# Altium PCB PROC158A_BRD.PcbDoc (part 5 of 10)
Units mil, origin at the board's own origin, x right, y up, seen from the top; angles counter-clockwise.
Board outline 3346.45 x 4921.26 mil, 8 copper layers (Top Layer, GND1, SIG1, PWR1, PWR2, SIG2, GND2, Bottom Layer), stack 54.534 mil thick; 718 components, 459 nets, 2307 pads, 1179 vias.
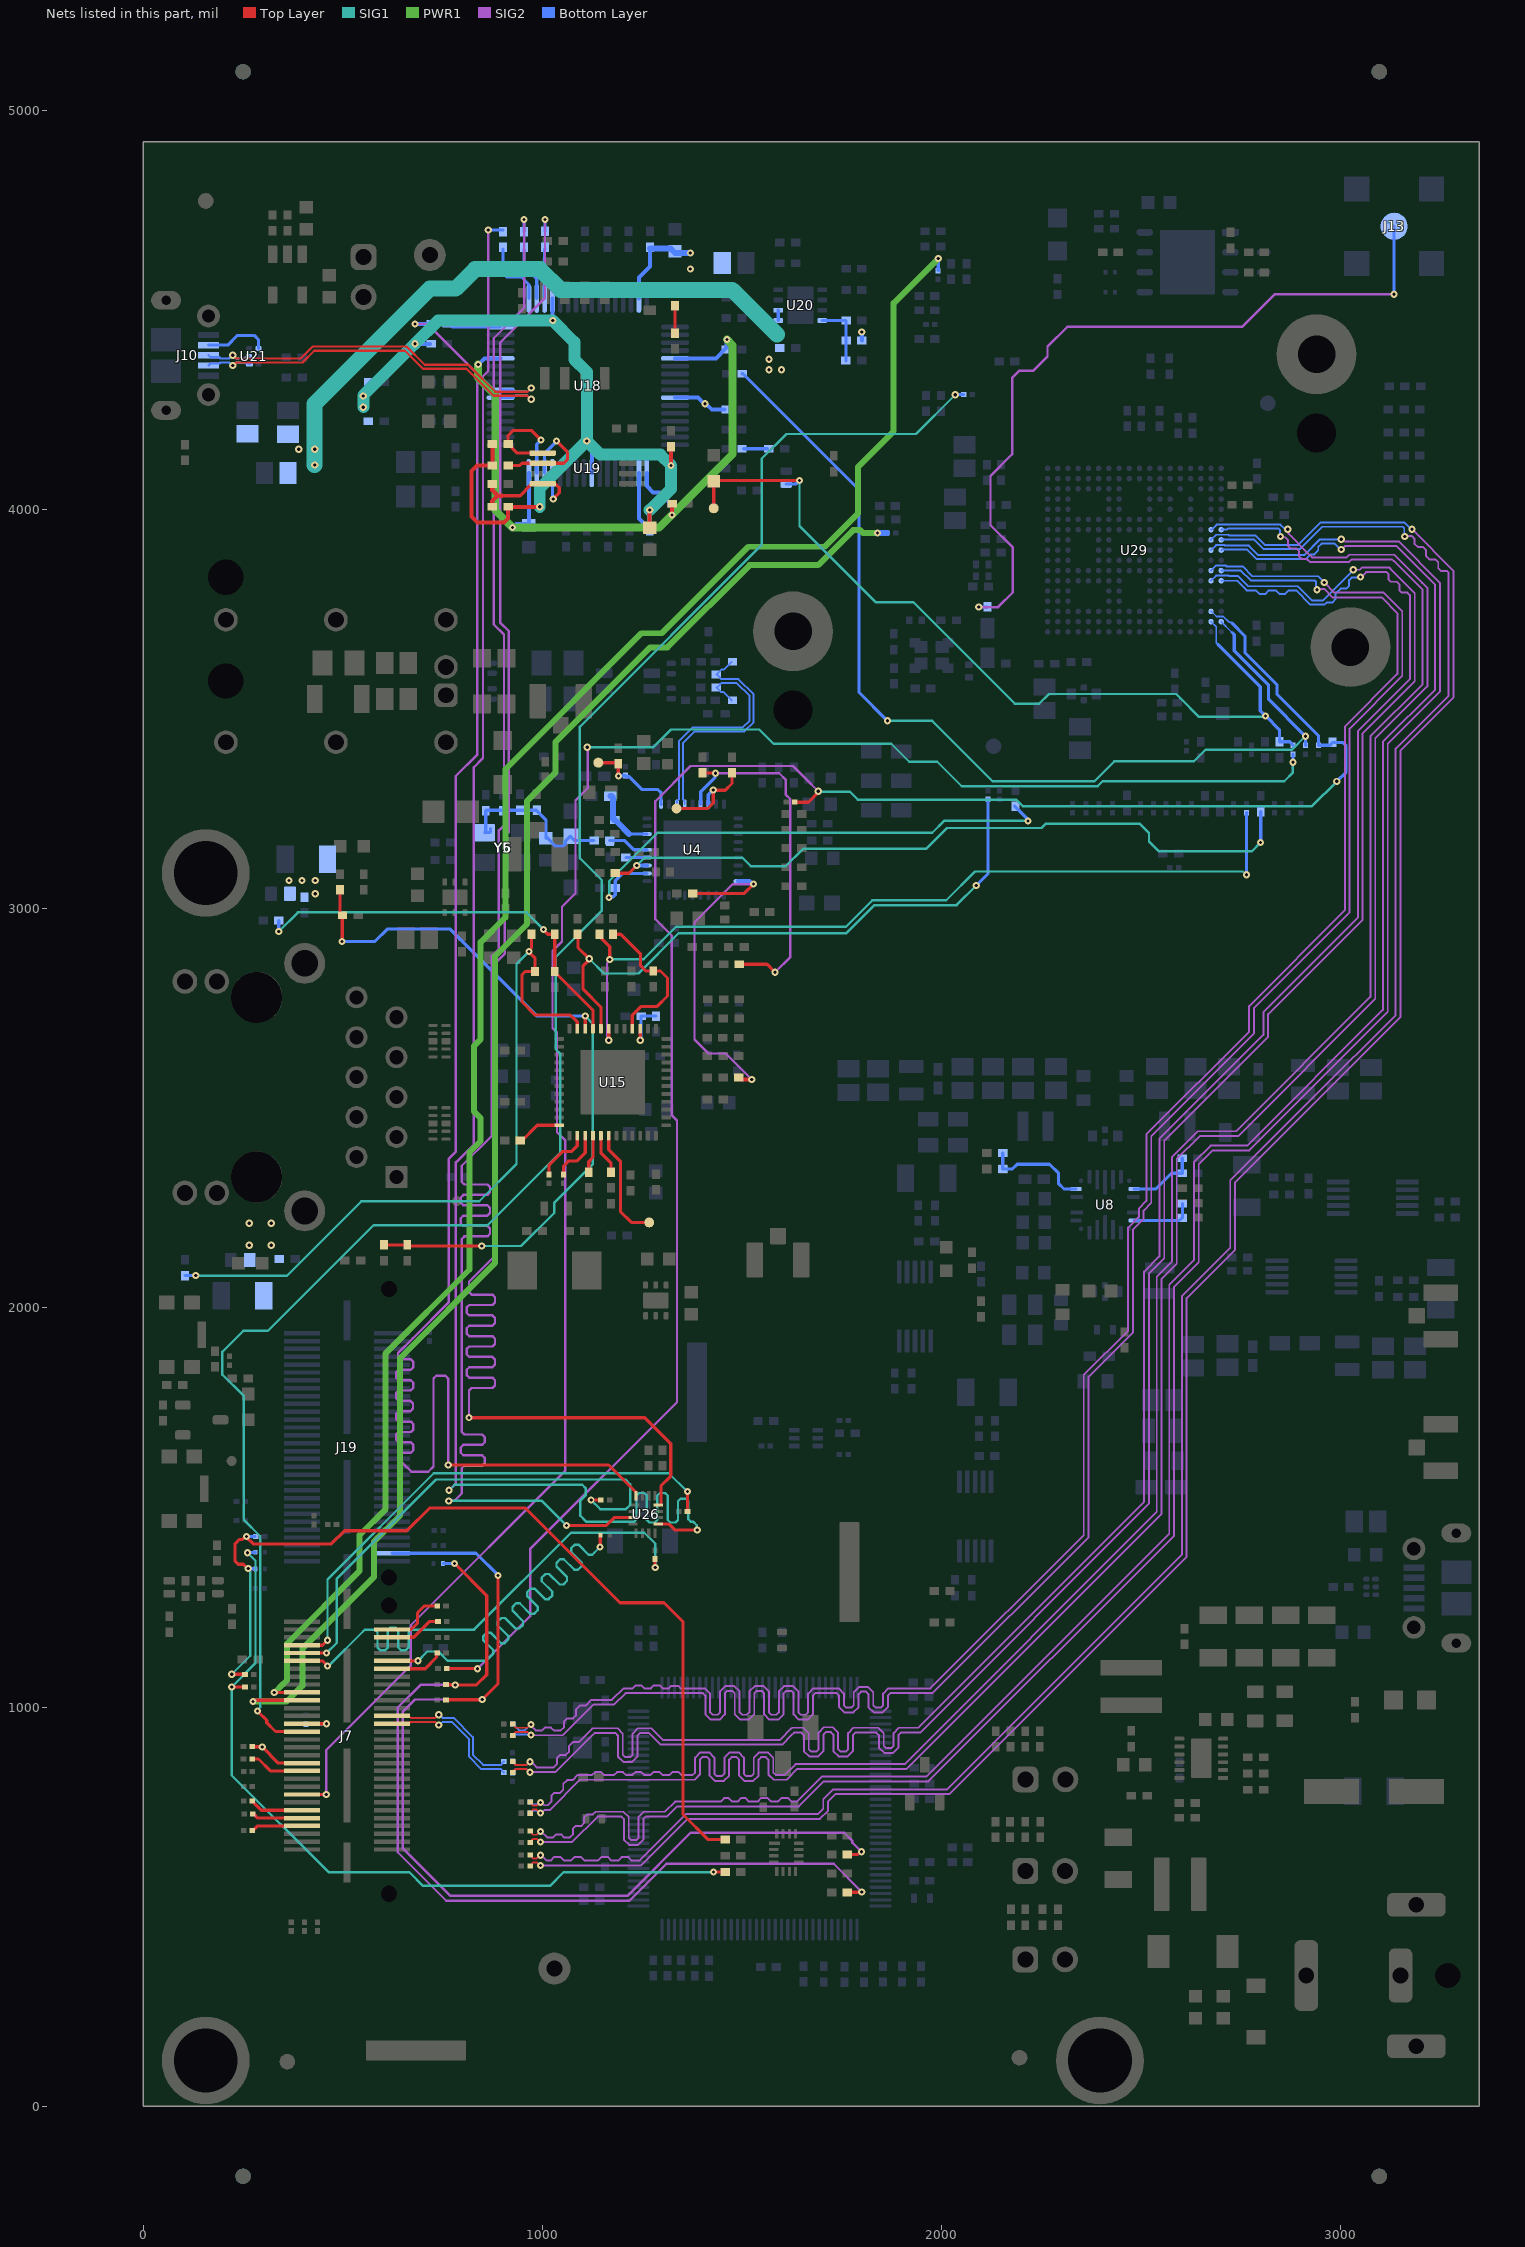
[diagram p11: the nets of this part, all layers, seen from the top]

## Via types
v1: diameter 18, hole 8, Top Layer to Bottom Layer, tented both sides, 1112 vias
v2: diameter 19.68, hole 7.87, Top Layer to Bottom Layer, 28 vias
v3: diameter 20, hole 10, Top Layer to Bottom Layer, tented both sides, 26 vias
v4: diameter 16/18/18/18/18/18/18/16 (per signal layer), hole 8, Top Layer to Bottom Layer, tented both sides, 13 vias

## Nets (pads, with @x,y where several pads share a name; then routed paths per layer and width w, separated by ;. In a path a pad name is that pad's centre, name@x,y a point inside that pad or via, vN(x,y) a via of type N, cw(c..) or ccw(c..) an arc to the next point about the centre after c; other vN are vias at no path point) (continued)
AR_SYNCIN: R17.2 R61.2 R78.2 R115.1 U29.C17 | length 4997.9
  Top Layer w8: R115.1@760.24,1096.36 760.37,1096.24 837.33,1096.24 v1(837.46,1096.11) ; R61.2@1632.43,3266.81 1666.52,3266.81 1691,3291.29 v1(1691,3294)
  SIG1 w6: v1(1691,3294) 1692.12,3292.88 1770.15,3292.88 1789.83,3273.2 2186.63,3273.2 2202.98,3256.85 2927.85,3256.85 v1(2990,3319)
  SIG2 w6: v1(837.46,1096.11) 969,1227.65 969,1395.67 1337,1763.67 1337,2469.46 1324.38,2482.07 1324.38,2932.02 1282.78,2973.62 1282.78,3269.18 1371.04,3357.44 1627.56,3357.44 1660.52,3324.48 v1(1691,3294)
  Bottom Layer w4: U29.C17@2674.75,3744.71 2675.76,3744.71 2688.59,3731.87 2705.63,3731.87 2720.25,3717.25 2725.26,3717.25 2727.51,3715
  Bottom Layer w8: 2727.51,3715 2760,3682.51 2760,3641 2840,3561 2840,3554.13 2840,3537.33 2944,3433.33 R78.2@2944,3409.35 2973.16,3409.35 2979,3415.19 R17.2@2979,3416.66 3004.34,3416.66 3013.13,3407.87 3013.13,3342.13 v1(2990,3319)
AR_WRMRST: D5.2 D9.2 R272.1 R371.1 TP1.1 U29.B17 | length 2231.1
  Top Layer w8: TP1.1@1429,4003 D9.2@1429.01,4070.65 ; D9.2@1429.01,4070.65 1431,4072.64 v1(1643.91,4072.64)
  SIG1 w6: v1(1643.91,4072.64) 1643.91,3958.57 1834.53,3767.95 1929.03,3767.95 2106.08,3590.91 2183.29,3513.7 2244.7,3513.7 2268.75,3537.75 2587.59,3537.75 2598.02,3527.32 2644.88,3480.47 2801.49,3480.47 2801.72,3480.71 2808.71,3480.71 v1(2811,3483)
  Bottom Layer w4: U29.B17@2674.75,3719.11 2687.58,3706.28 2687.58,3666.42 2691.97,3662.03
  Bottom Layer w8: D5.2@1610.48,4063.7 1634.98,4063.7 v1(1643.91,4072.64) ; 2691.97,3662.03 2798.05,3555.95 2798.05,3495.95 v1(2811,3483) 2811.49,3483 2846,3448.49 R272.1@2846,3418.01 2872.13,3418.01 2880,3410.14 R371.1@2880,3409.35
AR_WRMRST_FTDI: R330.2 R362.1 | length 59.5
  Bottom Layer w8: R330.2@1503.76,4152.19 R362.1@1563.24,4152.19
BAW_NC: C121.1 R168.2 R177.2 R185.1 R241.2 R242.2 R248.1 Y5.1 Y6.1 | length 427.8
  Bottom Layer w8: Y5.1@855.78,3190.24 858,3192.47 R185.1@858,3245.81 858.66,3246.47 985.34,3246.47 985.34,3245.82 1008.66,3222.49 R248.1@1008.66,3176.69 ; Y5.1@860.66,3190.84 868.98,3190.84 870.11,3191.97 Y5.1@870.11,3200.28 ; R248.1@1010.63,3178.66 1032.22,3157.07 1052.55,3157.07 1057.23,3161.76 1057.23,3168.55 1070,3181.32 1080.68,3170.64 R242.2@1129.31,3170.64
BSS_UARTA_TX: R131.1 R232.2 U29.B18 | length 2575.2
  SIG1 w6: v1(1864,3470.81) 1976.19,3470.81 2128.2,3318.8 2131.2,3318.8 2382.36,3318.8 2432.86,3369.3 2631.98,3369.3 2661.01,3398.33 2877.33,3398.33 v1@2911,3432
  Bottom Layer w4: U29.B18@2700.34,3719.11 2727.51,3691.95
  Bottom Layer w8: R131.1@1500.43,4339.96 1502.4,4339.96 1793,4049.36 1793,3541.81 v1(1864,3470.81) ; 2727.51,3691.95 2733,3686.45 2733,3646.12 2819.03,3560.09 2819.03,3524.24 v1(2911.13,3432.13) 2911.57,3431.7 2911.57,3409.78 R232.2@2912,3409.35
CLKP_SMA: J13.1 R269.2 | length 1933.9
  SIG2 w6: v1(2092.87,3755.57) 2141.57,3755.57 2178.5,3792.5 2178.5,3904.5 2122.5,3960.5 ; 2122.36,3960.5 2122.36,4084.11 2176.5,4138.25 2176.5,4329.15 2195.25,4347.89 2229.83,4347.89 2265.24,4383.3 2265.24,4407.9 2314.63,4457.3 2752.3,4457.3 2834,4539 v1(3133,4539)
  Bottom Layer w8: v1(2092.87,3755.57) 2093.02,3755.73 2114.71,3755.73 R269.2@2114.86,3755.88 ; v1(3133,4539) 3133.25,4539.25 3133.25,4709.25 J13.1@3133.5,4709.5
CSI2_TX0_LVDS_TX0_N: R366.2 U29.K17 | length 5430.1
  Top Layer w4.8: R366.2@969.05,602 969.83,602 973.73,605.9 973.73,608.09 976.55,610.9 985.59,610.9 993.49,603 v1(995,603)
  SIG2 w4.8: v1(995,603) 995.5,603.5 1247.52,603.5 1363.97,719.96 1694.86,719.96 1715.46,740.57 1715.46,763.49 1733.89,781.92 2019,781.92 2613.6,1376.52 2613.6,2024.7 2735,2146.1 2735,2314.56 2935.83,2515.38 3149,2728.56 3149,3396.03 3282,3529.03 3282,3846.28 3178.38,3949.9 v1(3178.38,3950.38)
  Bottom Layer w4.8: U29.K17@2674.75,3923.84 2687.55,3936.64 2718.59,3936.64 2719.89,3935.34 2786.09,3935.34 2810.68,3910.75 2892.56,3910.75 2948.78,3966.97 3159.81,3966.97 3176.4,3950.38 v1(3178.38,3950.38)
CSI2_TX0_LVDS_TX0_P: R365.2 U29.K18 | length 5429.4
  Top Layer w4.8: R365.2@969.05,630 969.83,630 973.73,626.1 973.73,623.91 976.55,621.1 985.59,621.1 993.49,629 v1(995,629)
  SIG2 w4.8: v1(995,629) 997.41,629 1010.91,615.5 1020.29,615.5 1028.79,624 1045.85,624 1054.35,615.5 1071.41,615.5 1079.91,624 1096.98,624 1105.48,615.5 1138.82,615.5 1147.32,624 1164.38,624 1172.88,615.5 1189.95,615.5 1198.45,624 1215.51,624 1224.01,615.5 1242.55,615.5 1359,731.96 1689.89,731.96 1703.46,745.54 1703.46,768.46 1728.92,793.92 2014.03,793.92 2601.6,1381.49 2601.6,2029.67 2723,2151.07 2723,2319.53 2930.85,2527.38 3137,2733.53 3137,3401 3270,3534 3270,3841.31 3264.88,3846.43 3250.43,3846.43 3244.04,3852.82 3244.04,3867.27 3236.31,3875 3221.86,3875 3213.5,3883.36 3213.5,3897.81 3205.05,3906.26 3192.71,3906.26 3184.42,3914.55 3184.42,3926.89 3178.56,3932.75 ; v1(3160,3932) 3161.98,3933.98 3177.33,3933.98
  Bottom Layer w4.8: U29.K18@2700.34,3923.84 2701.64,3925.14 2781.87,3925.14 2806.45,3900.55 2896.78,3900.55 2953,3956.77 3155.59,3956.77 3158.93,3953.42 3158.93,3933.07 v1(3160,3932)
CSI2_TX1_LVDS_TX1_N: R364.2 U29.J17 | length 5425.9
  Top Layer w4.8: R364.2@969.05,661.06 969.83,661.06 973.73,664.95 973.73,667.14 976.55,669.95 985.59,669.95 993.49,662.06 v1(995,662.06)
  SIG2 w4.8: v1@995.29,661.76 1073.86,661.76 1137.95,725.85 1172.99,725.85 1197.88,725.85 1204.08,719.65 1204.08,668.17 1217.31,654.94 1239.66,654.94 1252.88,668.17 1252.88,719.65 1259.08,725.85 1265,725.85 1311.65,725.85 1337.16,751.36 1642.18,751.36 1704.69,813.87 1966.75,813.87 2582.2,1429.32 2582.2,2052.75 2644,2114.55 2644,2360.19 2678.54,2394.73 2770.77,2394.73 3117.6,2741.56 3117.6,3413.57 3248.05,3544.02 3248.05,3816.51 3144.48,3920.08 3010.23,3920.08 3004.65,3925.66 v1(3001.07,3925.66)
  Bottom Layer w4.8: U29.J17@2674.75,3898.25 2687.55,3911.04 2708.37,3911.04 2709.66,3909.75 2769.68,3909.75 2793.68,3885.75 2908.35,3885.75 2947.44,3924.84 3000.25,3924.84 v1(3001.07,3925.66)
CSI2_TX1_LVDS_TX1_P: R363.2 U29.J18 | length 5424.9
  Top Layer w4.8: R363.2@969.05,689.06 969.83,689.06 973.73,685.16 973.73,682.97 976.55,680.16 985.59,680.16 993.49,688.06 v1(995,688.06)
  SIG2 w4.8: v1(995,688.06) 997.41,688.06 1011.71,673.76 1026.95,673.76 1034.14,680.95 1046.71,680.95 1053.9,673.76 1068.89,673.76 1076.67,681.54 1076.67,695.99 1082.57,701.9 1097.02,701.9 1104,708.88 1104,723.33 1111.89,731.21 1126.34,731.21 1132.98,737.85 1172.99,737.85 1202.86,737.85 1216.08,724.62 1216.08,673.14 1222.28,666.94 1234.68,666.94 1240.88,673.14 1240.88,724.62 1254.11,737.85 1265,737.85 1306.68,737.85 1332.19,763.36 1446.55,763.36 1455.05,771.86 1466.53,771.86 1475.03,763.36 1488.78,763.36 1497.28,771.86 1508.79,771.86 1517.29,763.36 1538.86,763.36 1547.36,771.86 1564.42,771.86 1572.92,763.36 1589.99,763.36 1598.49,771.86 1615.55,771.86 1624.05,763.36 1637.21,763.36 1699.72,825.87 1961.78,825.87 2570.2,1434.29 2570.2,2057.72 2632,2119.52 2632,2365.16 2673.57,2406.73 2765.8,2406.73 3105.6,2746.53 3105.6,3418.54 3236.05,3548.99 3236.05,3811.54 3139.51,3908.08 3010.49,3908.08 3002.07,3899.66 v1(3001.07,3899.66)
  Bottom Layer w4.8: U29.J18@2700.34,3898.25 2701.64,3899.55 2765.46,3899.55 2789.45,3875.55 2912.57,3875.55 2924.69,3887.66 2933.71,3887.66 2943.48,3897.44 2943.48,3906.46 2951.66,3914.64 2984.59,3914.64 2999.56,3899.66 v1(3001.07,3899.66)
CSI2_TX2_CLK_LVDS_FRCLK_N: R160.2 R323.2 R349.2 U29.F17 | length 5513.2
  Top Layer w4.8: R349.2@925.46,835.87 926.25,835.87 930.15,839.77 930.15,841.96 932.96,844.77 959.59,844.77 967.49,836.87 v1(969,836.87)
  SIG2 w4.8: v1(969,836.87) 969.21,837.08 1032.66,837.08 1124.52,928.93 1130.55,934.97 1183.05,934.97 1189.25,928.77 1189.25,875.65 1202.48,862.42 1224.82,862.42 1238.05,875.65 1238.05,928.77 1244.25,934.97 1250.17,934.97 1267.48,934.97 1296.45,906 1600.28,906 1623.8,929.51 1630.43,936.15 1648.92,936.15 1655.12,929.95 1655.12,889.9 1668.35,876.67 1690.69,876.67 1703.92,889.9 1703.92,931.25 1710.12,937.45 1722.52,937.45 1728.72,931.25 1728.72,889.9 1741.95,876.67 1764.29,876.67 1777.52,889.9 1777.52,929.95 1783.72,936.15 1789.63,936.15 1794.03,936.15 1836.74,936.15 1842.94,929.95 1842.94,898.38 1856.17,885.15 1878.51,885.15 1891.74,898.38 1891.74,929.95 1897.94,936.15 1939.07,936.15 1946.23,936.15 2519.4,1509.32 2519.4,2085.8 2557.6,2124 2557.6,2418.52 2818,2678.91 2818,2736 3054.49,2972.49 3054.49,3439.26 3185.25,3570.03 3185.25,3790.5 3123.99,3851.76 3120.71,3855.04 3053.32,3855.04 3047.28,3849 v1(3031,3849)
  Bottom Layer w4.8: R323.2@925.46,835.87 926.25,835.87 930.15,839.77 930.15,841.96 932.96,844.77 959.59,844.77 967.49,836.87 v1(969,836.87) ; U29.F17@2674.75,3821.48 2687.55,3834.27 2718.86,3834.27 2720.16,3832.97 2742.87,3832.97 2768.11,3807.73 2892.25,3807.73 2927.98,3772 2954.79,3772 3031,3848.21 v1(3031,3849)
CSI2_TX2_CLK_LVDS_FRCLK_P: R138.2 R322.2 R345.2 U29.F18 | length 5511.6
  Top Layer w4.8: R345.2@925.46,863.87 926.25,863.87 930.15,859.97 930.15,857.78 932.96,854.97 959.59,854.97 967.49,862.87 v1(969,862.87)
  SIG2 w4.8: v1(969,862.87) 971.41,862.87 985.21,849.08 1027.69,849.08 1036.93,858.32 1036.93,872.77 1044.47,880.31 1058.92,880.31 1066.79,888.18 1066.79,902.63 1076.41,912.25 1090.86,912.25 1124.52,945.9 1125.58,946.97 1188.02,946.97 1201.25,933.74 1201.25,880.62 1207.45,874.42 1219.85,874.42 1226.05,880.62 1226.05,933.74 1239.28,946.97 1250.17,946.97 1272.45,946.97 1301.42,918 1595.31,918 1623.8,946.48 1625.46,948.15 1653.89,948.15 1667.12,934.92 1667.12,894.87 1673.32,888.67 1685.72,888.67 1691.92,894.87 1691.92,936.22 1705.15,949.45 1727.49,949.45 1740.72,936.22 1740.72,894.87 1746.92,888.67 1759.32,888.67 1765.52,894.87 1765.52,934.92 1778.75,948.15 1789.63,948.15 1794.03,948.15 1841.71,948.15 1854.94,934.92 1854.94,903.35 1861.14,897.15 1873.54,897.15 1879.74,903.35 1879.74,934.92 1892.97,948.15 1939.07,948.15 1941.26,948.15 2507.4,1514.29 2507.4,2090.77 2545.6,2128.97 2545.6,2423.49 2806,2683.89 2806,2740.97 3042.49,2977.46 3042.49,3444.23 3173.25,3575 3173.25,3785.53 3166.95,3791.83 3152.5,3791.83 3147.4,3796.93 3147.4,3811.38 3139.74,3819.04 3125.29,3819.04 3119.06,3825.27 3119.06,3838.51 3114.53,3843.04 3063.27,3843.04 3050.84,3830.62 v1(3049.39,3830.62)
  Bottom Layer w4.8: R322.2@925.46,863.87 929.36,859.97 929.36,857.78 932.17,854.97 959.59,854.97 967.49,862.87 v1(969,862.87) ; U29.F18@2700.34,3821.48 2739.94,3821.48 2763.88,3797.53 2787.28,3797.53 2796.8,3788.01 2810.24,3788.01 2819.76,3797.53 2837.52,3797.53 2847.18,3787.87 2859.8,3787.87 2869.46,3797.53 2888.02,3797.53 2923.75,3761.8 2959.02,3761.8 2964.18,3766.97 2977.97,3766.97 2987.1,3776.1 2987.1,3789.89 2999.26,3802.04 3013.83,3802.04 3020.55,3808.77 3020.55,3823.33 3026.76,3829.55 3048.32,3829.55 v1(3049.39,3830.62)
CSI2_TX3_N: R167.2 R341.2 U29.G17 | length 5507.3
  Top Layer w4.8: R341.2@925.46,929 926.25,929 930.15,932.9 930.15,935.09 932.96,937.9 961.88,937.9 969.78,930 v1(971.29,930)
  SIG2 w4.8: v1(971.29,930) 971.88,929.42 1050.74,929.42 1127.29,1005.97 1179.14,1005.97 1208.16,1035 1401.9,1035 1408.1,1028.8 1408.1,981.89 1421.33,968.66 1443.67,968.66 1456.9,981.89 1456.9,1034.19 1463.1,1040.39 1475.5,1040.39 1481.7,1034.19 1481.7,981.89 1494.93,968.66 1517.27,968.66 1530.5,981.89 1530.5,1034.19 1536.7,1040.39 1549.1,1040.39 1555.3,1034.19 1555.3,981.89 1568.53,968.66 1590.87,968.66 1604.1,981.89 1604.1,1034.19 1610.3,1040.39 1622.7,1040.39 1628.9,1034.19 1628.9,981.89 1642.13,968.66 1664.47,968.66 1677.7,981.89 1677.7,1028.8 1683.9,1035 1736.92,1035 1743.12,1028.8 1743.12,1000.06 1756.35,986.83 1778.69,986.83 1791.92,1000.06 1791.92,1032.52 1798.12,1038.72 1810.52,1038.72 1816.72,1032.52 1816.72,1000.06 1829.95,986.83 1852.29,986.83 1865.52,1000.06 1865.52,1028.8 1871.72,1035 1976.97,1035 2368,1426.03 2368,1827 2479.1,1938.1 2479.1,2195.9 2506,2222.8 2506,2243.89 2525,2262.89 2525,2430.32 2782,2687.32 2782,2751.03 3022,2991.03 3022,3451.19 3153.85,3583.04 3153.85,3745.15 3146.82,3752.18 3145,3754 3107.06,3791.94 2983.84,3791.94 v1(2958.39,3817.39)
  Bottom Layer w4.8: R167.2@925.46,929 927.98,931.52 969.77,931.52 v1(971.29,930) ; U29.G17@2674.75,3847.07 2687.55,3859.86 2711.4,3859.86 2714,3857.27 2753.93,3857.27 2778.46,3832.73 2943.04,3832.73 v1(2958.39,3817.39)
CSI2_TX3_P: R164.2 R327.2 U29.G18 | length 5504.7
  Top Layer w4.8: R327.2@925.46,957 926.25,957 930.15,953.1 930.15,950.91 932.96,948.1 961.88,948.1 969.78,956 v1(971.29,956)
  SIG2 w4.8: v1(971.29,956) 971.29,953.19 983.07,941.42 999.03,941.42 1006.23,948.61 1021.08,948.61 1028.27,941.42 1045.77,941.42 1054.2,949.85 1054.2,964.3 1061.74,971.84 1076.19,971.84 1084.06,979.71 1084.06,994.17 1093.68,1003.78 1108.13,1003.78 1122.32,1017.97 1174.17,1017.97 1203.19,1047 1226,1047 1233.19,1054.19 1248.05,1054.19 1255.24,1047 1271.58,1047 1278.77,1054.19 1293.63,1054.19 1300.82,1047 1316.99,1047 1323.04,1053.04 1340.19,1053.04 1346.23,1047 1406.87,1047 1420.1,1033.77 1420.1,986.86 1426.3,980.66 1438.7,980.66 1444.9,986.86 1444.9,1039.16 1458.13,1052.39 1480.47,1052.39 1493.7,1039.16 1493.7,986.86 1499.9,980.66 1512.3,980.66 1518.5,986.86 1518.5,1039.16 1531.73,1052.39 1554.07,1052.39 1567.3,1039.16 1567.3,986.86 1573.5,980.66 1585.9,980.66 1592.1,986.86 1592.1,1039.16 1605.33,1052.39 1627.67,1052.39 1640.9,1039.16 1640.9,986.86 1647.1,980.66 1659.5,980.66 1665.7,986.86 1665.7,1033.77 1678.93,1047 1741.89,1047 1755.12,1033.77 1755.12,1005.03 1761.32,998.83 1773.72,998.83 1779.92,1005.03 1779.92,1037.49 1793.15,1050.72 1815.49,1050.72 1828.72,1037.49 1828.72,1005.03 1834.92,998.83 1847.32,998.83 1853.52,1005.03 1853.52,1033.77 1866.75,1047 1972,1047 2356,1431 2356,1831.97 2467.1,1943.07 2467.1,2200.87 2468.13,2201.9 2494,2227.77 2494,2248.86 2513,2267.86 2513,2435.29 2770,2692.29 2770,2756 3010,2996 3010,3456.16 3141.85,3588.01 3141.85,3740.18 3102.09,3779.94 2978.87,3779.94 2957.86,3800.94 2941.94,3800.94 v1(2940,3799)
  Bottom Layer w4.8: R164.2@925.46,957 926.25,957 941.53,941.72 955.5,941.72 969.78,956 v1(971.29,956) ; U29.G18@2700.34,3847.07 2749.71,3847.07 2774.24,3822.53 2934.13,3822.53 2937.48,3819.19 2937.48,3801.53 v1@2938.99,3800.02
CSI2_TX4_LVDS_CLK_N: R135.2 R361.2 U29.L17 | length 5491.3
  Top Layer w4.8: R361.2@969.05,734 969.83,734 973.73,737.9 973.73,740.09 976.55,742.9 985.59,742.9 993.49,735 v1(995,735)
  SIG2 w4.8: v1(995,735) 997.41,735 1004.41,742 1017.91,742 1093.76,817.85 1370.05,817.85 1380.94,817.85 1394.17,831.08 1394.17,868.4 1400.37,874.6 1412.77,874.6 1418.97,868.4 1418.97,828.06 1432.2,814.83 1454.54,814.83 1467.77,828.06 1467.77,868.4 1473.97,874.6 1486.37,874.6 1492.57,868.4 1492.57,828.06 1505.8,814.83 1528.14,814.83 1541.37,828.06 1541.37,868.4 1547.57,874.6 1559.97,874.6 1566.17,868.4 1566.17,831.08 1579.4,817.85 1602.81,817.85 1611.46,817.85 1638.89,845.27 1641.12,845.27 1912.32,845.27 2550.8,1483.75 2550.8,2072.8 2589,2111 2589,2372.96 2646.59,2430.55 2742.64,2430.55 3086.2,2774.11 3086.2,3426.57 3216.65,3557.02 3216.65,3803.51 3203.82,3816.34 3199.58,3820.58 3137,3883.16 3133.51,3886.65 3021.19,3886.65 3014.54,3880 2927.87,3880 2915.24,3892.64 2868.94,3938.93 2868.94,3948.83 v1(2867.24,3950.53)
  Bottom Layer w4.8: R135.2@969.05,734 969.83,734 976.18,740.35 986.08,740.35 991.43,735 v1(995,735) ; U29.L17@2674.75,3949.43 2676.04,3949.43 2688.84,3962.23 2848.52,3962.23 2857.69,3953.06 2864.71,3953.06 v1(2867.24,3950.53)
CSI2_TX4_LVDS_CLK_P: R51.2 R351.2 U29.L18 | length 5489.6
  Top Layer w4.8: R351.2@969.05,762 969.83,762 973.73,758.1 973.73,755.91 976.55,753.1 985.59,753.1 993.49,761 v1(995,761)
  SIG2 w4.8: v1(995,761) 997.41,761 1004.41,754 1012.94,754 1022.18,763.24 1022.18,777.69 1029.72,785.23 1044.17,785.23 1052.05,793.1 1052.05,807.56 1061.66,817.17 1076.11,817.17 1088.94,830 1124.76,830 1131.95,837.19 1146.81,837.19 1154.15,829.85 1179.67,829.85 1186.86,837.04 1201.72,837.04 1208.91,829.85 1225.25,829.85 1232.44,837.04 1247.3,837.04 1254.49,829.85 1270.83,829.85 1278.68,837.7 1292.23,837.7 1300.07,829.85 1318.59,829.85 1326.31,837.57 1340.11,837.57 1347.83,829.85 1370.05,829.85 1375.97,829.85 1382.17,836.05 1382.17,873.37 1395.4,886.6 1417.74,886.6 1430.97,873.37 1430.97,833.03 1437.17,826.83 1449.57,826.83 1455.77,833.03 1455.77,873.37 1469,886.6 1491.34,886.6 1504.57,873.37 1504.57,833.03 1510.77,826.83 1523.17,826.83 1529.37,833.03 1529.37,873.37 1542.6,886.6 1564.94,886.6 1578.17,873.37 1578.17,836.05 1584.37,829.85 1602.81,829.85 1606.49,829.85 1633.92,857.27 1907.35,857.27 2538.8,1488.72 2538.8,2077.77 2577,2115.97 2577,2377.93 2641.62,2442.55 2737.67,2442.55 3074.2,2779.08 3074.2,3431.54 3204.65,3561.99 3204.65,3798.54 3132.03,3871.16 3128.54,3874.65 3026.16,3874.65 3019.51,3868 2922.9,3868 2914.91,3875.99 2901.85,3875.99 2894.77,3883.07 2894.77,3896.13 2888.93,3901.97 2874.48,3901.97 2868.14,3908.31 2868.14,3922.76 2860.46,3930.44 2850.56,3930.44 v1(2848.85,3932.15)
  Bottom Layer w4.8: R51.2@969.05,762 969.83,762 976.18,755.65 986.08,755.65 991.43,761 v1(995,761) ; U29.L18@2700.34,3949.43 2714.54,3949.43 2717.14,3952.03 2844.3,3952.03 2847.84,3948.48 2847.84,3933.16 v1(2848.85,3932.15)
DBG_EPWMA0: J7.6 R81.2 | length 129.6
  Top Layer w8: J7.6@623.08,1174.67 677.23,1174.67 716.6,1214.04 R81.2@736.41,1214.04
DBG_GPADC1: J7.19 R80.2 | length 4537
  Top Layer w8: v1(328.26,1036.6) 328.4,1036.74 397.35,1036.74 J7.19@397.49,1036.88
  PWR1 w15: v1(328.26,1036.6) 329.07,1036.6 350.86,1058.38 351.21,1058.38 360,1067.17 360,1159 542.02,1341.02 542.02,1431.02 607,1496 607,1886 817.2,2096.2 817.2,2390.2 845,2418 845,2475.39 828.02,2492.37 828.02,2655.81 845,2672.8 845,2916 907.5,2978.5 907.5,3349.68 1247.82,3690 1299,3690 1515.68,3906.68 1707.03,3906.68 1789.91,3989.56 1789.91,4106.11 1880,4196.2 1880,4517.04 v1(1991.46,4628.5)
  Bottom Layer w8: R80.2@1991.38,4598.49 R80.2@1991.38,4598.49 1991.42,4628.46 v1(1991.46,4628.5)
DBG_GPADC2: J7.21 R82.2 | length 3944.3
  Top Layer w8: v1(274.75,1013.81) 277.46,1013.81 280.84,1017.19 J7.21@397.49,1017.19
  PWR1 w15: v1(274.75,1013.81) 275.04,1014.1 359.36,1014.1 398.37,1053.11 398.37,1146.21 577.83,1325.67 577.83,1414.43 643,1479.6 643,1874.23 881.67,2112.91 881.67,2881.57 961.81,2961.71 961.81,3269.92 1032.5,3340.61 1032.5,3417.32 1269.77,3654.59 1313.02,3654.59 1518.92,3860.5 1690.54,3860.5 1778.39,3948.35 1795.84,3948.35 1803.19,3941 v1(1839,3941)
  Bottom Layer w15: v1(1839,3941) R82.2@1862.86,3940.97
DBG_GPADC5: J7.27 R91.2 | length 112.7
  Top Layer w8: J7.27@397.49,958.14 v1@458.81,958.14
  Bottom Layer w8: R91.2@408.16,957.34 458.41,957.34 v1(459.21,958.14)
DBG_GPADC6: J7.29 R94.2 | length 4706.5
  Top Layer w8: v1(285.91,990.12) 309.55,966.48 309.55,960.45 331.27,938.73 397.22,938.73 J7.29@397.49,938.45
  SIG1 w6: v1(285.91,990.12) 285.91,992.45 293.09,999.63 293.09,1427.72 251.97,1468.84 251.97,1779 198,1832.97 198,1889.83 250.83,1942.65 312.48,1942.65 576.86,2207.04 862.47,2207.04 1044.12,2388.69 1044.12,2637.01 1033.22,2647.91 1033.22,2879.33 1149,2995.11 1149,3071.19 1093.5,3126.68 1093.5,3455.5 1549,3911 1549,4127.06 1610.94,4189 1935.6,4189 v1(2034,4287.4)
  Bottom Layer w8: v1(2034,4287.4) 2034.3,4287.7 2054.65,4287.7 R94.2@2054.95,4288
DBG_I2CA_SCL: J7.51 R390.2 | length 125.2
  Top Layer w8: R390.2@276.62,732.43 287.13,721.92 J7.51@397.49,721.92
DBG_I2CA_SDA: J7.53 R391.2 | length 126.8
  Top Layer w8: R391.2@275.33,690.95 286.62,702.23 J7.53@397.49,702.23
DBG_NERROUT: J7.49 R379.2 | length 133.7
  Top Layer w8: R379.2@273.38,763.55 274.17,763.55 276.47,761.25 276.47,760.46 295.33,741.6 J7.49@397.49,741.6
DBG_SPI_CLK: J7.9 R399.2 | length 1289.1
  Top Layer w8: J7.9@397.49,1135.3 v1@458.81,1135.3 ; v1(1122,1518.81) 1122.1,1518.92 1146.17,1518.92 R399.2@1146.28,1519.02
  SIG1 w6: v1(459.21,1135.3) 484.95,1161.05 484.95,1321.95 733,1570 1208.26,1570 1219.98,1558.28 1219.98,1506.61 1209.34,1495.96 1144.85,1495.96 v1(1122,1518.81)
DBG_SPI_CS0: J7.7 R223.2 | length 1301.8
  Top Layer w8: J7.7@397.49,1154.99 448.98,1154.99 v1(461.49,1167.5) ; v1(1363,1540) 1363.24,1539.76 1363.24,1490.55 R223.2@1363.48,1490.31
  SIG1 w6: v1(461.49,1167.5) 461.49,1319.65 727.66,1585.81 1316.56,1585.81 v1@1362.69,1539.69
DBG_SPI_MISO: J7.12 R377.1 | length 1283.3
  Top Layer w8: J7.12@623.08,1115.62 623.18,1115.72 687.9,1115.72 v1(688,1115.81) ; v1(1144.07,1400.81) 1144.78,1401.52 1144.78,1429.56 R377.1@1145.49,1430.27
  SIG1 w6: v1(688,1115.81) 711.4,1139.21 739.29,1139.21 762.69,1115.81 859.07,1115.81 874.56,1131.3 876.68,1133.42 876.68,1142.62 851.31,1167.99 851.31,1177.18 860.5,1186.37 869.7,1186.37 896.07,1160 905.26,1160 914.45,1169.19 914.45,1178.39 888.08,1204.76 888.08,1213.95 897.27,1223.14 906.47,1223.14 932.84,1196.77 942.03,1196.77 951.22,1205.96 951.22,1215.16 924.85,1241.53 924.85,1250.72 934.04,1259.91 943.23,1259.91 969.61,1233.54 978.8,1233.54 987.99,1242.73 987.99,1251.93 961.62,1278.3 961.62,1287.49 970.81,1296.68 980,1296.68 1006.38,1270.31 1015.57,1270.31 1024.76,1279.5 1024.76,1288.69 998.39,1315.07 998.39,1324.26 1007.58,1333.45 1016.77,1333.45 1043.15,1307.08 1052.34,1307.08 1061.53,1316.27 1061.53,1325.46 1035.16,1351.84 1035.16,1361.03 1044.35,1370.22 1053.54,1370.22 1079.92,1343.85 1089.11,1343.85 1098.3,1353.04 1098.3,1362.23 1071.93,1388.61 1071.93,1397.8 1081.12,1406.99 1090.31,1406.99 1115.69,1381.62 1124.88,1381.62 1129.77,1386.51 v1(1144.07,1400.81)
DBG_SPI_MOSI: J7.11 R188.2 | length 1304.5
  Top Layer w8: J7.11@397.49,1115.62 448.98,1115.62 v1(461.49,1103.1) ; R188.2@1281.93,1371.01 1282.25,1370.69 1282.25,1350.19 v1(1282.57,1349.87)
  SIG1 w6: v1(461.49,1103.1) 464.18,1103.1 551.17,1190.1 555.07,1194 580.17,1194 586.67,1187.5 586.67,1149.29 593.17,1142.79 606.17,1142.79 612.67,1149.29 612.67,1192.15 619.17,1198.65 632.17,1198.65 638.67,1192.15 638.67,1149.29 645.17,1142.79 658.17,1142.79 664.67,1149.29 664.67,1187.5 671.17,1194 682.64,1194 828.76,1194 1071.57,1436.81 1255.19,1436.81 1282.57,1409.43 v1(1282.57,1349.87)
DBG_SPIB_CS1: J7.37 R215.2 | length 141.5
  Top Layer w8: R215.2@273.02,900.81 273.43,900.41 297.59,900.41 338.29,859.71 J7.37@397.49,859.71
  other v1: 298,900
DBG_SPIB_CS2: J7.39 R324.2 | length 136.8
  Top Layer w8: R324.2@273.02,869.81 288.61,869.81 318.39,840.03 J7.39@397.49,840.03
DBG_WRMRST: J7.45 R371.2 | length 4889
  Top Layer w8: J7.45@397.49,780.97 J7.45@397.49,780.97 458.54,781.01 v1(458.58,781.05)
  SIG1 w6: v1(1112.26,3404.51) 1112.77,3404 1277,3404 1321.91,3448.91 1543.09,3448.91 1579,3413 1873.81,3413 1918.7,3368.11 1988.93,3368.11 2050.46,3306.58 2143.42,3306.58 2390.59,3306.58 2403.33,3319.32 2598.02,3319.32 2858.32,3319.32 2880,3341 v1(2880,3366.77)
  SIG2 w6: v1(458.58,781.05) 458.58,892.52 670,1103.94 670,1205.07 1057.37,1592.44 1057.37,2419.14 1036.47,2440.04 1036.47,2689.82 1025.08,2701.22 1025.08,2893.66 1048.99,2917.58 1048.99,3004.81 1082.71,3038.53 1082.71,3271.07 1113.26,3301.62 1113.26,3403.51 v1(1112.26,3404.51)
  Bottom Layer w8: v1(2880,3366.77) R371.2@2880,3387.3
DBG_XREF_CLK0: J7.4 R84.2 | length 150.6
  Top Layer w8: J7.4@623.08,1194.36 623.28,1194.55 671.24,1194.55 686.87,1210.19 686.87,1235.8 704.48,1253.41 R84.2@734.26,1253.41
DBG_XREF_CLK1: J7.14 R90.2 | length 135.4
  Top Layer w8: J7.14@623.08,1095.93 706.2,1095.93 734.44,1124.18 734.44,1134.3 735.44,1135.3 R90.2@736.23,1135.3
EECLK: R184.1 U18.62 U19.2 | length 305.2
  Top Layer w8: R184.1@914.04,4110.54 943.57,4110.54 948.69,4115.65 U19.2@1000.42,4115.65 1053.71,4115.65 1062.57,4124.51 1062.57,4144.37 v1(1035.47,4171.47)
  Bottom Layer w8: U18.62@1005.4,4091.18 1005.4,4141.4 v1(1035.47,4171.47)
EECS: R187.1 U18.63 U19.1 | length 301.7
  Top Layer w8: v1(996.49,4173.72) 972.16,4198.05 926.82,4198.05 914.04,4185.27 R187.1@914.04,4164.3 937.09,4141.24 U19.1@1000.42,4141.24
  Bottom Layer w8: U18.63@985.72,4091.18 985.72,4162.96 v1(996.49,4173.72)
EEDATA: R201.1 R205.1 U18.61 U19.4 | length 339.9
  Top Layer w8: 898.81,4034.54 943.93,4034.54 970.96,4061.57 973.85,4064.47 1032.39,4064.47 1042.07,4054.79 1042.07,4041.69 v1(1026.82,4026.45)
  Top Layer w10.6: R201.1@874.67,4006.75 874,4007.42 874,4021.3 887.24,4034.54 888.06,4034.54 ; R205.1@874.67,4063.55 874.1,4062.98 874.1,4048.5 888.06,4034.54 ; 898.81,4034.54 888.06,4034.54
  Bottom Layer w8: U18.61@1025.09,4091.18 1025.09,4028.18 v1(1026.82,4026.45)
EMU_TCK: R244.1 R354.1 R375.2 R422.1 | length 2349.2
  Top Layer w8: v1(221.63,1082.03) R422.1@252.91,1082.03 ; v1(263.09,1347.02) 261.09,1347.02 250.27,1357.84 237.56,1357.84 230.07,1365.33 230.07,1409.52 240.36,1419.82 248.06,1419.82 255.63,1427.39 v1(258.33,1427.39) 258.33,1425.59 275.11,1408.81 471.22,1408.81 504.34,1441.93 660.5,1441.93 716.93,1498.36 957.46,1498.36 1194.26,1261.56 1304.44,1261.56 1352,1214 1352,730.81 1414.23,668.58 R354.1@1457.48,668.58
  SIG1 w6: v1(221.63,1082.03) 268,1128.4 268,1338.87 263.09,1343.78 v1(263.09,1347.02)
  Bottom Layer w8: v1(258.33,1427.39) 258.55,1427.6 279.46,1427.6 R244.1@279.67,1427.81 ; v1(263.09,1347.02) 263.59,1346.53 280.19,1346.53 R375.2@280.68,1346.03
EMU_TDI: R356.1 R376.2 R423.1 | length 2006.8
  Top Layer w8: v1(221.63,1050.53) R423.1@252.91,1050.53 ; v1(1428.49,586.58) R356.1@1457.48,586.58
  SIG1 w6: v1(261.16,1386.5) 281.09,1366.57 281.09,1110 v1(221.63,1050.53) 221.63,828.99 464.03,586.58 666.23,586.58 700.81,552 1018.78,552 1053.35,586.58 v1(1428.49,586.58)
  Bottom Layer w8: v1(261.16,1386.5) 261.97,1387.3 279.93,1387.3 280.68,1388.05 R376.2@280.68,1388.1
EMU_TDO: J19.4 R360.1 R425.2 | length 2585.8
  Top Layer w8: R425.2@758.27,1017.19 759.18,1018.1 848.1,1018.1 v1(849,1019) 889,1059 v1(889,1329.81) ; R360.1@1763.89,630.4 1764.19,630.7 1789.41,630.7 1796.22,637.51 v1(1798.93,637.51)
  SIG2 w6: v1(849,1019) 680.83,1019 649.61,987.77 649.61,647.05 769.65,527 1117,527 1213,527 1371.04,685.04 1756.12,685.04 1776.37,664.78 1776.37,660.06 v1(1798.93,637.51)
  Bottom Layer w8: J19.4@623.08,1385.38 833.43,1385.38 v1(889,1329.81)
EMU_TMS: R358.1 R374.1 R424.2 | length 2300
  Top Layer w8: R424.2@758.27,1056 758.47,1055.8 781.57,1055.8 v1(781.76,1055.6) 834.72,1055.6 860.3,1081.18 860.3,1279.07 v1(779.8,1359.57) ; R358.1@1763.89,535.58 1764.6,536.29 1799.29,536.29 v1(1800,537)
  SIG2 w6: v1(781.76,1055.6) 694.6,1055.6 637.61,998.61 637.61,636.39 759,515 1117,515 1217.97,515 1310.39,607.42 1729.58,607.42 v1(1800,537)
  Bottom Layer w8: R374.1@751.09,1359.57 v1(779.8,1359.57)
ERTH_GND: C27.2 C28.2 R119.1 R130.1 R401.2 R419.2
  other v1: 265.38,2156.78 320.78,2156.78 265.38,2212.18 320.78,2212.18 430.82,3037.47 365.05,3070.35 397.94,3070.35 430.82,3070.35
ETH1_INT_PWDN: R224.2 R340.1 U15.44 | length 1578.6
  Top Layer w8: R340.1@1087.72,2935.84 1088.96,2934.6 1088.96,2902.63 v1(1117.08,2874.51) ; v1@1117.08,2874.94 v1(1117.08,2874.51) ; U15.44@1146.4,2699.4 1146.4,2753.75 1101.22,2798.93 1101.22,2855.77 1113.38,2867.93 1113.38,2868.81 1117.08,2872.51 v1(1117.08,2874.51)
  SIG1 w6: v1(1117.08,2874.51) 1153.95,2837.65 1240.39,2837.65 1341.47,2938.73 1761.23,2938.73 1831.51,3009 2037.6,3009 v1(2086.57,3057.97)
  Bottom Layer w8: v1(2086.57,3057.97) 2116.08,3087.48 2116.08,3270.87 2116,3270.95 R224.2@2116,3273.95
ETH1_NRST: R229.2 R342.1 U15.43 | length 2154.2
  Top Layer w8: R342.1@1143.2,2935.84 1147.74,2931.3 1147.74,2925.95 1168.73,2904.96 v1(1168.73,2872.86) ; v1@1166.09,2670.87 U15.43@1166.09,2699.4
  SIG1 w6: v1(1168.73,2872.86) 1169.7,2873.82 1253.94,2873.82 1334.96,2954.85 1760.39,2954.85 1826.54,3021 2011.55,3021 2083.59,3093.03 2754.49,3093.03 2762.52,3085 v1(2764,3085)
  SIG2 w6: v1(1166.09,2670.57) 1166.09,2673.82 1161.71,2678.19 1161.71,2754.21 1161.71,2863.34 1168.73,2870.37 v1(1168.73,2872.86)
  Bottom Layer w8: v1(2764,3085) v1(2764,3085) 2764.05,3240.18 R229.2@2764.1,3240.22
ETH2_CLKOUT: R254.1 TP2.1 U4.16 | length 252.4
  Top Layer w8: TP2.1@1336,3251 1414.03,3251 1427.71,3264.68 v1(1427.71,3297.59) 1428.62,3296.68 1457.91,3296.68 1474.75,3313.52 R254.1@1474.75,3340.36
  Bottom Layer w8: U4.16@1415.57,3261.74 1415.57,3285.45 v1(1427.71,3297.59)
ETH2_EN: C40.1 R11.2 U4.7 | length 156.4
  Bottom Layer w8: 1217.31,3186.94 U4.7@1262.03,3186.94
  Bottom Layer w15: C40.1@1170,3281.81 1172.89,3281.81 1177.2,3277.5 1177.2,3224.63 1179.54,3222.28 R11.2@1181.43,3222.28 ; R11.2@1185.74,3218.5 1217.31,3186.94
ETH2_INH: R12.2 R251.1 TP3.1 U4.10 | length 236.8
  Top Layer w8: TP3.1@1140,3365.81 1187,3365.81 1190.09,3362.73 1190.09,3332.29 v1(1190.17,3332.2)
  Bottom Layer w8: v1(1190.17,3332.2) 1190.97,3333.01 1207.2,3333.01 R12.2@1208,3333.81 1208,3333.02 1210.3,3330.72 1217.39,3330.72 1249.92,3298.19 1289.38,3298.19 1297.2,3290.37 1297.2,3262 U4.10@1297.46,3261.74
ETH2_INT: R22.1 R34.2 U4.2 | length 1343.2
  SIG1 w6: v1(1167,3028) 1167,3068.57 1288.58,3190.14 1976.36,3190.14 2006.22,3220 v1(2216,3220)
  Bottom Layer w8: v1(1167,3028) 1168.91,3029.91 1177.52,3029.91 1182.57,3034.96 1182.57,3069.73 1201.35,3088.51 U4.2@1262.03,3088.51 ; R22.1@2182.86,3256.63 2183.03,3256.63 2190.84,3248.82 2190.84,3248.65 2214.09,3225.41 2214.09,3221.91 v1(2216,3220)
ETH2_NRST: R23.1 R46.2 U4.3 | length 1838.5
  Top Layer w8: R46.2@1182.57,3088.99 1216.82,3088.99 v1(1236.03,3108.2)
  SIG1 w6: v1(1236.03,3108.2) 1255.25,3127.42 1500.98,3127.42 1521.79,3106.6 1609.6,3106.6 1652.93,3149.93 1961.22,3149.93 2013.29,3202 2250.48,3202 2261.48,3213 2496.04,3213 2519.56,3189.48 2519.56,3168.53 2544.41,3143.67 2776.67,3143.67 v1(2799,3166)
  Bottom Layer w8: v1(2799,3166) 2799.19,3166.19 2799.19,3242.82 R23.1@2799.39,3243.02
  Bottom Layer w10: v1(1236.03,3108.2) U4.3@1262.03,3108.2
ETH2_RX_CLK: R15.1 R234.2 U4.27 | length 904
  Top Layer w8: R15.1@1376.2,3038.39 1505.31,3038.39 v1(1528.58,3061.66)
  Top Layer w10: R234.2@1491.78,2577.02 1496.62,2572.18 1504.36,2572.18 1504.45,2572.1 v1(1524.45,2572.1)
  SIG2 w6: v1(1524.45,2572.1) 1459.34,2637.21 1415.74,2637.21 1380.93,2672.03 1380.93,2965.93 1476.66,3061.66 v1(1528.58,3061.66)
  Bottom Layer w10: U4.27@1490.38,3068.83 1519.25,3068.83 1526.41,3061.66 v1(1528.58,3061.66)
ETH2_RX_CTRL: R245.2 R252.1 U4.15 | length 911
  Top Layer w8: R252.1@1401.29,3336.43 1404.77,3339.9 1433.4,3339.9 v1(1433.86,3339.44) ; R245.2@1493.07,2860.81 1562.65,2860.81 v1(1582.65,2840.81)
  SIG2 w6: v1(1433.86,3339.44) 1593.23,3339.44 1609.15,3323.52 1609.15,3286.21 1621.18,3274.18 1621.18,2879.34 v1(1582.65,2840.81)
  Bottom Layer w8: U4.15@1395.89,3261.74 1396.66,3262.51 1396.66,3292.77 1431.95,3328.06 1431.95,3337.53 v1(1433.86,3339.44)
ETH2_XI: R186.1 R242.1 U4.5 | length 102.9
  Bottom Layer w8: R242.1@1168.68,3170.64 1192.18,3170.64 ; 1192.19,3170.64 1205.95,3170.64 1229.02,3147.57 U4.5@1262.03,3147.57
ETH2_XO: R246.2 U4.4 | length 86.9
  Bottom Layer w8: R246.2@1209.05,3128.27 1209.24,3128.07 1261.84,3128.07 U4.4@1262.03,3127.88 1228.3,3127.88
ETH_CLK_OUT: TP5.1 U15.18 | length 285.8
  Top Layer w8: U15.18@1166.09,2431.68 1166.09,2396.59 1195.36,2367.31 1195.36,2241.47 1222.74,2214.09 TP5.1@1267.43,2214.09
ETH_GPIO0: R139.1 R143.2 U15.39 | length 126.5
  Top Layer w8: v1(1244.83,2670.57) U15.39@1244.83,2699.1
  Bottom Layer w8: v1(1244.83,2670.57) 1247.11,2672.86 1247.11,2697.56 R139.1@1247.11,2730.46 1247.59,2730.93 R143.2@1284.09,2730.93
ETH_GPIO1: R141.1 R142.2 U15.40 | length 385.6
  Top Layer w8: R141.1@1177,2936.13 1195.69,2936.13 1245.92,2885.89 1245.92,2856.89 1258.87,2843.94 R142.2@1277.72,2843.94 1295.64,2843.94 1313.21,2826.37 1313.21,2781.35 1287.07,2755.21 1247.89,2755.21 1224.83,2733.02 1224.83,2699.72 U15.40@1225.14,2699.4
ETH_LED0: R68.1 R92.1 R97.2 U15.47 | length 1871
  Top Layer w8: R92.1@972.5,2935.91 972.5,2901.17 966.11,2894.78 966.11,2890.78 981.55,2875.34 981.55,2849.11 981.5,2849.06 R97.2@981.5,2846.54 ; R97.2@981.5,2842.6 956.9,2842.6 948.66,2834.36 948.66,2766.55 981.65,2733.56 1070.06,2733.56 1079.41,2724.21 1087.35,2716.27 U15.47@1087.35,2699.4
  SIG1 w6: v1(131.64,2080.92) 131.91,2080.65 359.95,2080.65 546.34,2267.04 841.76,2267.04 935,2360.28 935,2861.67 v1(966.11,2892.78)
  Bottom Layer w8: R68.1@104.25,2080.85 104.29,2080.89 v1(131.64,2080.92) v1(131.64,2080.92)
ETH_LED1: R112.1 R113.1 R117.2 R118.2 U15.46 | length 1875.3
  Top Layer w8: R113.1@493.11,3047.15 493.11,2989.5 R112.1@499.02,2983.6 498.62,2983.2 498.62,2918.25 v1(498.22,2917.85) ; R117.2@603.35,2157.62 R118.2@661.43,2157.62 664.06,2155 v1(848,2155) ; U15.46@1107.03,2699.4 v1@1107.03,2727.93
  SIG1 w6: v1(848,2155) 946.53,2155 1029.95,2238.42 1029.95,2263.7 1126.47,2360.22 1126.47,2711.49 v1(1107.03,2730.93)
  Bottom Layer w8: v1(498.22,2917.85) 580.17,2917.85 611.14,2948.82 768.89,2948.82 986.78,2730.93 v1(1107.03,2730.93)
ETH_LED2: R69.2 R132.1 R137.2 U15.45 | length 1039.8
  Top Layer w8: v1(1003,2948) 1003,2946.29 1013.49,2935.8 1030.54,2935.8 R132.1@1030.65,2935.91 1030.65,2840.63 1036.49,2834.79 1037.69,2834.79 1126.72,2745.76 U15.45@1126.72,2699.4
  SIG1 w6: v1(339.37,2942.75) 387.43,2990.81 960.19,2990.81 v1(1003,2948)
  Bottom Layer w8: v1(339.37,2942.75) 339.57,2942.95 339.57,2970.2 R69.2@339.78,2970.41
ETH_MDI_CLK: R369.1 U15.16 | length 96.2
  Top Layer w8: R369.1@1116.04,2339.86 1116.04,2366.3 1126.72,2376.98 U15.16@1126.72,2431.68
ETH_MDI_DATA: R413.1 U15.17 | length 102.2
  Top Layer w8: U15.17@1146.4,2431.68 1146.4,2388.33 1171.49,2363.24 R413.1@1171.49,2339.86
ETH_RBIAS: R337.1 U15.12 | length 109.3
  Top Layer w8: R337.1@948.66,2418.89 987.04,2457.27 U15.12@1042.07,2457.27
ETH_TRD_N: C156.2 R265.1 U4.13 | length 589.2
  Bottom Layer w4.8: U4.13@1356.52,3261.74 1356.52,3269.22 1351.78,3273.96 1351.78,3414.78 1381,3444 1505.79,3444 1528.97,3467.17 ; C156.2@1474.07,3618.51 1454.22,3598.67 1448.13,3598.67 R265.1@1435.86,3586.4 1437.83,3586.4 1445.28,3578.96 1445.28,3578.17 1448.09,3575.36 1490.65,3575.36 1528.97,3537.04 1528.97,3467.26
ETH_TRD_P: C162.1 R270.1 U4.12 | length 572.4
  Bottom Layer w4.8: U4.12@1336.83,3261.74 1336.83,3269.22 1341.58,3273.96 1341.58,3419 1376.78,3454.2 1501.57,3454.2 1518.77,3471.4 1518.77,3532.82 1486.42,3565.16 1448.09,3565.16 1445.28,3562.35 1445.28,3561.57 1437.83,3554.12 R270.1@1435.86,3554.12 1447.64,3542.34 1453.74,3542.34 C162.1@1474.07,3522.02
ETH_XI: R344.2 U15.15 | length 132.2
  Top Layer w8: R344.2@1052.75,2334.19 1052.75,2355.11 1065.88,2368.24 1086.8,2368.24 1107.03,2388.47 U15.15@1107.03,2431.68
ETH_XO: R370.2 U15.14 | length 140.2
  Top Layer w8: R370.2@1016.02,2334.19 1016.02,2357.08 1051.06,2392.12 1073.57,2392.12 1087.35,2405.89 U15.14@1087.35,2431.68
FB_B1: R14.1 R67.1 U8.2 | length 174.4
  Bottom Layer w8: U8.2@2482.32,2297.68 2536.24,2297.68 2575.77,2337.21 R67.1@2602.73,2337.21 R14.1@2602.73,2374.81
FB_B2: R20.1 R71.1 U8.18 | length 269.4
  Bottom Layer w8: R71.1@2152.69,2387.81 2152.84,2387.65 2152.84,2347.97 R20.1@2153,2347.81 2177.17,2347.81 2188.98,2359.62 2270.16,2359.62 2292.97,2336.82 2292.97,2311.13 2306.41,2297.68 U8.18@2336.65,2297.68
FB_B3: R70.1 R291.1 U8.6 | length 159.1
  Bottom Layer w8: U8.6@2482.32,2218.94 2595.16,2218.94 2601.03,2224.81 R291.1@2603,2224.81 R70.1@2603,2260.81
FRCLK_N: J7.28 R323.1 | length 368.6
  Top Layer w4.8: J7.28@623.08,958.14 626.18,961.23 668.76,961.23 670.41,962.88 731,962.88 738.9,954.98 v1(740.41,954.98)
  Bottom Layer w4.8: v1(740.41,954.98) 741.92,954.98 749.82,962.88 773.29,962.88 815.8,920.37 815.8,876.22 847.25,844.77 895.92,844.77 898.73,841.96 898.73,839.77 902.63,835.87 R323.1@903.42,835.87
FRCLK_P: J7.26 R322.1 | length 368.6
  Top Layer w4.8: J7.26@623.08,977.82 626.18,974.73 668.76,974.73 670.41,973.08 731,973.08 738.9,980.98 v1(740.41,980.98)
  Bottom Layer w4.8: v1(740.41,980.98) 741.92,980.98 749.82,973.08 777.52,973.08 826,924.6 826,880.45 851.48,854.97 895.92,854.97 898.73,857.78 898.73,859.97 902.63,863.87 R322.1@903.42,863.87
FTDI_3V3: C87.1 C88.1 C89.1 C90.1 C91.1 L3.1 L4.1 R163.1 R181.2 R182.2 R184.2 R187.2 R201.2 U18.20 U18.31 U18.42 U18.50 U18.56 | length 2780.1
  Top Layer w10: R187.2@874.67,4164.3 R184.2@874.67,4110.54 835.5,4110.54 821.92,4096.95 821.92,3982.7 837.22,3967.39 903.42,3967.39 914.04,3978.01 R201.2@914.04,4006.75 v1(993.24,4006.75) ; v1(1268.73,3998.43) v1(1268.73,3998.43) C90.1@1268.76,3958.06 ; R181.2@1322.15,4153.61 1322.15,4110.61 v1(1322.22,4110.54)
  SIG1 w30: v1(551.26,4256.2) v1(551.26,4284.43) ; v1@551.26,4285.91 v1(680.38,4415.03) 738.42,4473.08 1025.29,4473.08 v1(1025.77,4473.56) 1080,4419.33 1080,4375.82 1111.12,4344.7 v1(1111.12,4171.47) ; v1(993.24,4006.75) 993.24,4053.59 v1(1111.12,4171.47) ; v1(1268.73,3998.43) 1322.22,4051.92 v1(1322.22,4110.54) 1295.52,4137.24 1145.35,4137.24 v1(1111.12,4171.47)
  Bottom Layer w10: v1(680.38,4415.03) R163.1@717.82,4415.03 ; U18.20@1025.09,4528.19 1025.43,4527.85 1025.43,4473.9 v1(1025.77,4473.56) ; v1(1111.12,4171.47) 1123.52,4159.08 U18.56@1123.52,4091.18 ; U18.50@1241.63,4091.18 1241.63,3977.33 1268.76,3950.19 v1(1268.73,3998.43) v1(1268.73,3998.43) ; U18.31@1241.63,4528.19 1241.63,4580.74 1269.17,4608.29 C88.1@1269.17,4653.39 ; U18.42@1332.18,4280.16 1390.02,4280.16 1405.33,4264.86 1409.66,4264.86 1424.13,4250.39 C89.1@1456.49,4250.39
  Bottom Layer w15: C88.1@1269.17,4653.39 1321.32,4653.39 1332.18,4642.54 v1(1370.48,4642.54)
  other v1: 1407.49,4264.86 1370.48,4602.54
FTDI_LDO_EN: R73.1 R183.1 R204.2 U20.8 | length 160.4
  Bottom Layer w8: U20.8@1701.01,4473.42 R204.2@1760.66,4473.42 R183.1@1760.66,4423.56 1760.49,4423.39 1760.49,4372.98 R73.1@1760.32,4372.81
FTDI_MISO: R146.1 U18.18 | length 137.5
  Bottom Layer w8: R146.1@954.16,4652.62 954.16,4610 985.72,4578.44 U18.18@985.72,4528.19
FTDI_MOSI: R145.1 U18.17 | length 172.9
  Bottom Layer w8: R145.1@900.95,4652.65 900.95,4592.09 910.72,4582.33 947.43,4582.33 966.03,4563.72 U18.17@966.03,4528.19
FTDI_SPI_CLK: R144.2 U26.16 | length 4481
  Top Layer w8: v1(763.8,1606.47) 1165.64,1606.47 U26.16@1234.62,1537.49
  SIG2 w6: v1(681.1,4464.57) 711.98,4464.57 837,4339.54 837,3386.21 782.57,3331.79 782.57,2390.57 764.99,2372.99 764.99,2013.7 675.33,1924.04 638.04,1886.75 638.04,1877.56 644.54,1871.06 670.33,1871.06 676.83,1864.56 676.83,1851.56 670.33,1845.06 639.5,1845.06 633,1838.56 633,1825.56 639.5,1819.06 669.68,1819.06 676.18,1812.56 676.18,1799.56 669.68,1793.06 639.5,1793.06 633,1786.56 633,1773.56 639.5,1767.06 669.14,1767.06 675.64,1760.56 675.64,1747.56 669.14,1741.06 639.5,1741.06 633,1734.56 633,1721.56 639.5,1715.06 670.33,1715.06 676.83,1708.56 676.83,1695.56 670.33,1689.06 639.5,1689.06 633,1682.56 633,1669.56 639.5,1663.06 670.33,1663.06 676.83,1656.56 676.83,1643.56 670.33,1637.06 646.23,1637.06 639.73,1630.56 639.73,1621.37 653.04,1608.06 671.61,1589.49 714.04,1589.49 727,1602.45 727,1823 734,1830 757,1830 763.8,1823.2 v1(763.8,1606.47)
  Bottom Layer w10: v1(681.1,4464.57) 681.52,4464.98 721.34,4464.98 R144.2@721.76,4465.4
FTDI_SPI_CS0: R147.2 U26.12 | length 4446.9
  Top Layer w8: v1(816,1725) 1256.23,1725 1321.47,1659.76 1321.47,1578.65 1296.99,1554.17 U26.12@1296.99,1506.12
  SIG2 w6: v1(816,1725) 816,1763.81 816,1792.81 822.5,1799.31 874.67,1799.31 881.17,1805.81 881.17,1818.81 874.67,1825.31 816.5,1825.31 810,1831.81 810,1844.81 816.5,1851.31 874.67,1851.31 881.17,1857.81 881.17,1870.81 874.67,1877.31 816.5,1877.31 810,1883.81 810,1896.81 816.5,1903.31 874.67,1903.31 881.17,1909.81 881.17,1922.81 874.67,1929.31 816.5,1929.31 810,1935.81 810,1948.81 816.5,1955.31 874.67,1955.31 881.17,1961.81 881.17,1974.81 874.67,1981.31 816.5,1981.31 810,1987.81 810,2000.81 816.5,2007.31 874.67,2007.31 881.17,2013.81 881.17,2026.81 874.67,2033.31 822.5,2033.31 816,2039.81 816,2044.69 816,2065.46 886.17,2135.63 886.17,2867.59 906,2887.41 906,3182 915.57,3191.57 915.57,3695.46 893.97,3717.06 893.97,4417.6 1006.27,4529.89 v1(1006.27,4726.24)
  Bottom Layer w8: v1@1006.01,4725.71 1006.27,4725.45 R147.2@1006.27,4696.66
FTDI_SPI_MISO: R146.2 U26.3 | length 4435.9
  Top Layer w8: v1(1060,1454.81) 1159.9,1454.81 1179.64,1474.56 U26.3@1226.81,1474.56
  SIG1 w6: v1(765.23,1516.36) 998.46,1516.36 v1(1060,1454.81)
  SIG2 w6: v1(765.23,1516.36) 778.95,1516.36 798,1535.4 798,1569.27 798,1598.27 804.5,1604.77 848.77,1604.77 855.27,1611.27 855.27,1624.27 848.77,1630.77 801.65,1630.77 795.15,1637.27 795.15,1650.27 801.65,1656.77 848.77,1656.77 855.27,1663.27 855.27,1676.27 848.77,1682.77 804.5,1682.77 798,1689.27 798,1714.32 798,2143.62 798,2172.62 804.5,2179.12 862.2,2179.12 868.7,2185.62 868.7,2198.62 862.2,2205.12 801.94,2205.12 795.44,2211.62 795.44,2224.62 801.94,2231.12 862.2,2231.12 868.7,2237.62 868.7,2250.62 862.2,2257.12 801.94,2257.12 795.44,2263.62 795.44,2276.62 801.94,2283.12 862.2,2283.12 868.7,2289.62 868.7,2302.62 862.2,2309.12 804.5,2309.12 798,2315.62 798,2324 798,2355.92 873.06,2430.98 873.06,2881.87 891,2899.81 891,3196 903.57,3208.57 903.57,3686.87 878.15,3712.29 878.15,4428.92 954.1,4504.88 v1(954.1,4726.24)
  Bottom Layer w8: R146.2@954.16,4695.92 v1(954.1,4726.24)
FTDI_SPI_MOSI: R145.2 U26.9 | length 4444.6
  Top Layer w8: U26.9@1289.8,1458.81 1316.1,1458.81 1331.1,1443.81 v1(1388,1443.81)
  SIG1 w6: v1(766.23,1543.1) 780.13,1557 1099.55,1557 1108,1548.55 1108,1530.27 1095,1517.27 1095,1479.42 1110.42,1464 1226.18,1464 1229.18,1464 1235.68,1470.5 1235.68,1529.88 1242.18,1536.38 1255.18,1536.38 1261.68,1529.88 1261.68,1468.74 1268.18,1462.24 1281.18,1462.24 1287.68,1468.74 1287.68,1529.88 1294.18,1536.38 1307.18,1536.38 1313.68,1529.88 1313.68,1468.74 1320.18,1462.24 1333.18,1462.24 1339.68,1468.74 1339.68,1515.5 1346.18,1522 1359.18,1522 1365.68,1515.5 1365.68,1470.5 1372.18,1464 1376.04,1464 1378,1464 1386.37,1455.63 1386.37,1445.45 v1(1388,1443.81)
  SIG2 w6: v1(766.23,1543.1) 783.15,1560.03 783.15,2364.33 828,2409.17 828,3354.1 851,3377.1 851,4333.85 864.15,4347 v1(864.15,4699.86)
  Bottom Layer w8: v1(864.15,4699.86) R145.2@900.92,4699.86
FTDI_SPICLK: R144.1 U18.16 | length 133.4
  Bottom Layer w8: R144.1@765.07,4465.4 773.14,4457.32 U18.16@895.17,4457.32
FTDI_SPICS: R147.1 U18.19 | length 125.5
  Bottom Layer w8: U18.19@1005.4,4528.19 1005.4,4652.49 R147.1@1006.27,4653.35
FTDI_SUSPEND_N: R179.2 R180.2 | length 61.3
  Top Layer w8: R179.2@1332.18,4445.51 R180.2@1332.18,4506.81
FTDI_USBD_N: J10.2 U18.7 U21.1 | length 1011
  Top Layer w5.65: v1(224,4360.42) 225.58,4360.42 233.48,4368.32 398.89,4368.32 428.56,4397.98 655.21,4397.98 659.27,4393.92 700.72,4352.47 809.65,4352.47 877.22,4284.9 962.68,4284.9 971.58,4276 v1(972.16,4276)
  Bottom Layer w5.65: J10.2@163.39,4360.62 168.44,4365.67 191.13,4365.67 193.78,4368.32 214.52,4368.32 222.42,4360.42 v1(224,4360.42) 225.58,4360.42 233.48,4368.32 254.09,4368.32 255.96,4366.45 263.61,4366.45 U21.1@265.99,4364.07 ; U18.7@895.17,4280.16 926.34,4280.16 931.09,4284.9 962.68,4284.9 971.58,4276 v1(972.16,4276)
FTDI_USBD_P: J10.3 U18.8 U21.2 | length 1010.4
  Top Layer w5.65: v1(224,4386.42) 225.58,4386.42 233.48,4378.52 394.67,4378.52 424.33,4408.18 659.43,4408.18 704.94,4362.67 813.87,4362.67 819.85,4356.7 820.89,4355.66 881.44,4295.1 962.68,4295.1 971.58,4304 v1(972.16,4304)
  Bottom Layer w5.65: J10.3@163.39,4386.21 168.44,4381.16 191.13,4381.16 193.78,4378.52 214.52,4378.52 222.42,4386.42 v1(224,4386.42) 225.58,4386.42 233.48,4378.52 253.11,4378.52 255.96,4381.37 262.62,4381.37 U21.2@265.01,4383.75 ; U18.8@895.17,4299.84 926.34,4299.84 931.09,4295.1 962.68,4295.1 971.58,4304 v1(972.16,4304)
FTDI_USBID: J10.4 U21.4 | length 161.5
  Bottom Layer w8: J10.4@163.39,4411.8 211.88,4411.8 236.13,4436.05 277.79,4436.05 288.63,4425.21 U21.4@288.63,4403.44
FTDI_VBUS: C39.1 C85.1 R183.2 R206.2 R207.2 U20.1 U20.2 | length 1565.3
  SIG1 w40: v1(429.39,4111.18) v1(429.39,4151.08) 429.39,4264.91 717.66,4553.18 782.4,4553.18 831.14,4601.93 993.63,4601.93 1045.37,4550.19 1475.38,4550.19 1587.01,4438.56
  Bottom Layer w8: U20.1@1590.78,4473.42 U20.2@1590.78,4499.01
  Bottom Layer w10: v1(1799.93,4444.6) 1799.98,4444.55 R183.2@1800.03,4423.56 R183.2@1800.03,4423.56
  other v1: 389.39,4151.08 1567.54,4350.15 1598.67,4350.15 1567.54,4376.52
FTDI_VCORE: C77.1 C78.1 C79.1 C82.1 U18.12 U18.37 U18.49 U18.64 | length 1929.7
  Top Layer w10: v1(1324.34,3986.37) 1324.83,3986.86 1324.83,4013.93 C78.1@1325.31,4014.41
  PWR1 w20: v1(839,4363) 838.21,4362.21 838.21,4330.22 881.75,4286.69 881.75,3998.1 v1(925.28,3954.56) 1292.53,3954.56 1476.38,4138.41 1476.38,4411.43 v1(1462,4425.81)
  Bottom Layer w10: v1(839,4363) 854.24,4378.24 894.82,4378.24 U18.12@895.17,4378.58 ; v1(925.28,3954.56) 934.69,3963.97 965.97,3963.97 965.97,4091.11 U18.64@966.03,4091.18 ; U18.49@1261.31,4091.18 1261.31,4058.86 1277.42,4042.75 1293.04,4042.75 1324.83,4010.96 1324.83,3986.86 v1(1324.34,3986.37) ; U18.37@1332.18,4378.58 1434.39,4378.58 1461.22,4405.41 1461.22,4425.03 v1(1462,4425.81)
